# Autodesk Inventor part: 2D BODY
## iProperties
Category: PART
Company: Cross Bros.
Shininess: 64.0
Length Units: 11272
Angle Units: 11279
Time Units: 11290
Mass Units: 11286
Length Display Precision: 3
Angle Display Precision: 2
Compacted: True
Part Number: 2D BODY
Document SubType Name: Modeling
Created: 2003-03
Designer: MVF
Catalog Web Link: www.crossbros.com
Density: 0.0
Volumn: 0.0
Area: 0.0
PropertySet Name: Model Information
Control State: 0
Master: False
Checked Out: False
HAND_LEN: 7.700 in
ELBOW_TO_WRIST: 9.800 in
SHOULDER_TO_ELBOW: 9.800 in
FOOT_LEN: 10.500 in
KNEE_TO_FOOT: 19.600 in
PELVIS_TO_KNEE: 15.400 in
PELVIS_WD: 14.000 in
SHOULDER_WD: 17.500 in
TORSO_HT: 23.450 in
HEAD_HT: 10.500 in
HEIGHT: 70.000 in
HEAD_JAW_WD: 5.292 in
HEAD_TOP_WD: 7.350 in
NECK_HT: 1.050 in
TORSO_BOT_THK: 6.843 in
ANKLE_THK: 3.592 in
SHOULDER_THK: 5.233 in
WRIST_THK: 2.355 in
TORSO_TOP_THK: 8.050 in
ELBOW_THK: 3.140 in
KNEE_THK: 4.790 in
HAND_THK: 1.413 in
LEG_TOP_THK: 6.843 in
Author: MVF
Title: iMike
